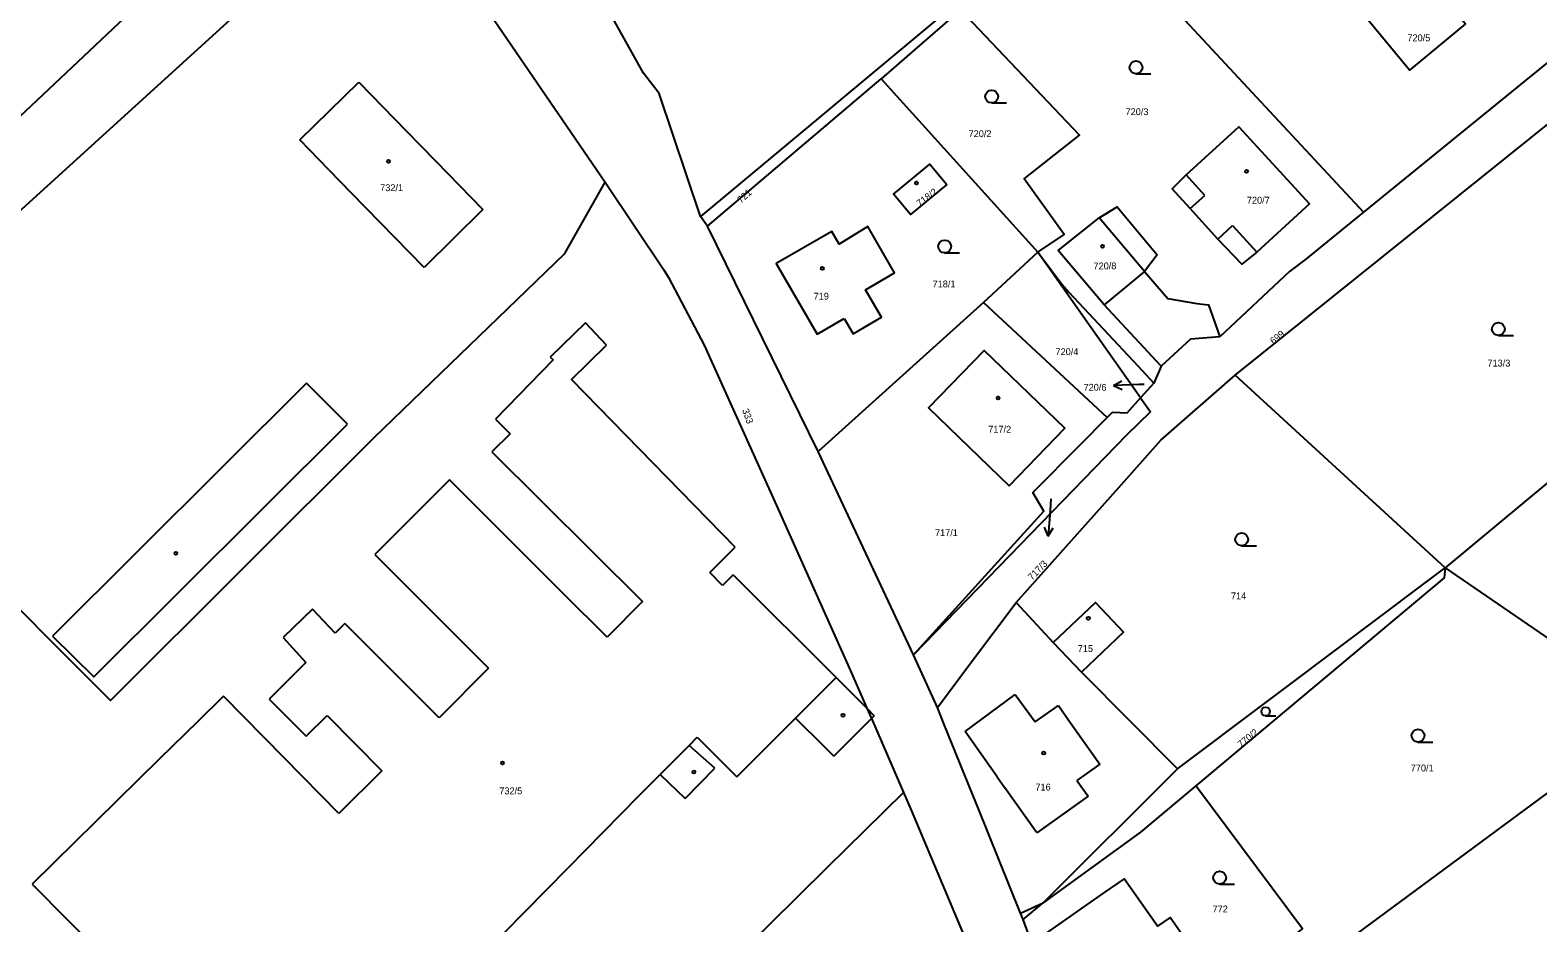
# Model space of a CAD drawing. Extents: x -719706 to -718922, y -950351 to -949651.
# Drawn here: x -719485 to -719308.7, y -949961.1 to -949856.8 of the extents above; entities that cross this region are included whole.
import ezdxf

# ---------------------------------------------------------------- set-up
doc = ezdxf.new("R2010")
doc.units = 0
doc.layers.add('Doplňující texty', color=7, linetype='Continuous')

msp = doc.modelspace()

# ---------------------------------------------------------------- linework, layer by layer
at = {"layer": 'Doplňující texty'}
for p, q in [((-719339.21, -949822.33), (-719406.63, -949878.59)), ((-719452.8, -949835.44), (-719497.78, -949877.76)), ((-719442.6, -949838.3), (-719510.6, -949900.1)), ((-719442.6, -949838.3), (-719417.75, -949874.56)), ((-719362.32, -949842.36), (-719329.12, -949878.08)), ((-719376.23, -949854.42), (-719385.52, -949862.47)), ((-719301.23, -949855.39), (-719329.12, -949878.08)), ((-719355.71, -949861.9), (-719353.96, -949861.9)), ((-719453.47, -949869.63), (-719446.57, -949862.89)), ((-719446.57, -949862.89), (-719440.99, -949868.6)), ((-719405.82, -949879.72), (-719385.52, -949862.47)), ((-719385.52, -949862.47), (-719367.2, -949882.75)), ((-719372.58, -949865.31), (-719370.83, -949865.31)), ((-719344.12, -949897.13), (-719306.59, -949867.02)), ((-719440.99, -949868.6), (-719437.57, -949872.1)), ((-719450.06, -949873.13), (-719453.47, -949869.63)), ((-719437.57, -949872.1), (-719432.08, -949877.76)), ((-719450.06, -949873.13), (-719447.46, -949875.79)), ((-719347.66, -949876.12), (-719349.85, -949873.72)), ((-719438.93, -949884.52), (-719447.46, -949875.79)), ((-719349.38, -949877.65), (-719347.66, -949876.12)), ((-719432.08, -949877.76), (-719438.93, -949884.52)), ((-719405.82, -949879.72), (-719406.63, -949878.59)), ((-719392.88, -949906.02), (-719405.82, -949879.72)), ((-719354.71, -949885), (-719360.03, -949878.73)), ((-719346.13, -949881.21), (-719344.43, -949879.64)), ((-719344.43, -949879.64), (-719341.58, -949882.74)), ((-719378.08, -949882.83), (-719376.33, -949882.83)), ((-719367.2, -949882.75), (-719373.55, -949888.61)), ((-719355.18, -949899.78), (-719367.2, -949882.75)), ((-719354.71, -949885), (-719359.44, -949888.89)), ((-719373.55, -949888.61), (-719392.88, -949906.02)), ((-719373.55, -949888.61), (-719359.07, -949902.04)), ((-719420.05, -949891.01), (-719424.19, -949895.01)), ((-719417.61, -949893.61), (-719420.05, -949891.01)), ((-719421.7, -949897.6), (-719417.61, -949893.61)), ((-719313.34, -949892.47), (-719311.59, -949892.47)), ((-719423.85, -949895.34), (-719430.59, -949902.25)), ((-719424.19, -949895.01), (-719423.85, -949895.34)), ((-719352.75, -949896.05), (-719353.61, -949898.05)), ((-719319.57, -949919.64), (-719344.12, -949897.13)), ((-719452.67, -949898.04), (-719482.37, -949927.62)), ((-719447.88, -949902.85), (-719452.67, -949898.04)), ((-719402.57, -949917.19), (-719421.7, -949897.6)), ((-719358.33, -949898.32), (-719357.35, -949897.78)), ((-719355.33, -949898.21), (-719358.33, -949898.32)), ((-719358.33, -949898.32), (-719357.31, -949898.78)), ((-719354.74, -949898.19), (-719355.33, -949898.21)), ((-719353.61, -949898.05), (-719355.18, -949899.78)), ((-719430.59, -949902.25), (-719428.89, -949903.95)), ((-719477.56, -949932.34), (-719447.88, -949902.85)), ((-719428.89, -949903.95), (-719431.02, -949906.08)), ((-719431.02, -949906.08), (-719413.39, -949923.54)), ((-719381.72, -949929.77), (-719392.88, -949906.02)), ((-719435.97, -949909.34), (-719444.69, -949918.08)), ((-719422.67, -949922.61), (-719435.97, -949909.34)), ((-719365.65, -949911.58), (-719365.75, -949912.92)), ((-719365.75, -949912.92), (-719365.96, -949915.91)), ((-719365.96, -949915.91), (-719366.39, -949914.88)), ((-719365.96, -949915.91), (-719365.39, -949914.95)), ((-719444.69, -949918.08), (-719431.39, -949931.35)), ((-719405.55, -949920.18), (-719402.57, -949917.19)), ((-719343.36, -949917.05), (-719341.61, -949917.05)), ((-719404.04, -949921.68), (-719405.55, -949920.18)), ((-719350.86, -949943.1), (-719319.57, -949919.64)), ((-719402.81, -949920.44), (-719404.04, -949921.68)), ((-719402.81, -949920.44), (-719390.78, -949932.44)), ((-719417.54, -949927.72), (-719422.67, -949922.61)), ((-719413.39, -949923.54), (-719417.54, -949927.72)), ((-719369.73, -949923.66), (-719365.41, -949928.34)), ((-719452, -949924.47), (-719455.42, -949927.78)), ((-719449.33, -949927.25), (-719452, -949924.47)), ((-719448.22, -949926.14), (-719449.33, -949927.25)), ((-719437.18, -949937.16), (-719448.22, -949926.14)), ((-719482.37, -949927.62), (-719477.56, -949932.34)), ((-719455.42, -949927.78), (-719452.75, -949930.68)), ((-719365.41, -949928.34), (-719362.09, -949931.8)), ((-719452.75, -949930.68), (-719457.04, -949934.98)), ((-719378.91, -949935.94), (-719381.72, -949929.77)), ((-719431.39, -949931.35), (-719437.18, -949937.16)), ((-719395.53, -949937.19), (-719390.78, -949932.44)), ((-719390.78, -949932.44), (-719387.18, -949936.03)), ((-719362.09, -949931.8), (-719350.86, -949943.1)), ((-719375.69, -949938.74), (-719369.82, -949934.44)), ((-719369.82, -949934.44), (-719367.48, -949937.63)), ((-719462.38, -949934.6), (-719465.36, -949937.52)), ((-719455.28, -949941.83), (-719462.38, -949934.6)), ((-719457.04, -949934.98), (-719452.72, -949939.31)), ((-719387.18, -949936.03), (-719386.31, -949936.9)), ((-719367.48, -949937.63), (-719364.77, -949935.72)), ((-719364.77, -949935.72), (-719363.55, -949937.45)), ((-719465.36, -949937.52), (-719469.87, -949941.95)), ((-719452.72, -949939.31), (-719450.25, -949936.88)), ((-719450.25, -949936.88), (-719443.88, -949943.36)), ((-719402.36, -949944.04), (-719395.53, -949937.19)), ((-719395.53, -949937.19), (-719392.13, -949940.55)), ((-719391.04, -949941.63), (-719386.65, -949937.24)), ((-719386.31, -949936.9), (-719386.65, -949937.24)), ((-719363.55, -949937.45), (-719362.69, -949938.66)), ((-719340.55, -949936.91), (-719339.37, -949936.91)), ((-719407.96, -949940.37), (-719407, -949939.41)), ((-719407, -949939.41), (-719402.36, -949944.04)), ((-719371.95, -949944.03), (-719375.69, -949938.74)), ((-719362.69, -949938.66), (-719359.93, -949942.56)), ((-719407.96, -949940.37), (-719411.35, -949943.77)), ((-719404.96, -949943.04), (-719407.96, -949940.37)), ((-719391.04, -949941.63), (-719392.13, -949940.55)), ((-719322.75, -949939.98), (-719321, -949939.98)), ((-719469.87, -949941.95), (-719484.76, -949956.58)), ((-719448.91, -949948.31), (-719455.28, -949941.83)), ((-719408.42, -949946.56), (-719404.96, -949943.04)), ((-719366.57, -949958.76), (-719350.86, -949943.1)), ((-719359.93, -949942.56), (-719362.62, -949944.46)), ((-719443.88, -949943.36), (-719448.91, -949948.31)), ((-719413.86, -949946.31), (-719411.35, -949943.77)), ((-719411.35, -949943.77), (-719408.42, -949946.56)), ((-719371.95, -949944.03), (-719371.04, -949945.32)), ((-719362.62, -949944.46), (-719361.31, -949946.31)), ((-719413.86, -949946.31), (-719422.15, -949954.73)), ((-719367.32, -949950.57), (-719371.04, -949945.32)), ((-719361.31, -949946.31), (-719367.32, -949950.57)), ((-719432.15, -949964.86), (-719422.15, -949954.73)), ((-719484.76, -949956.58), (-719458.38, -949983.18)), ((-719345.93, -949956.58), (-719344.18, -949956.58)), ((-719369.21, -949959.98), (-719366.57, -949958.76)), ((-719368.91, -949960.71), (-719366.57, -949958.76)), ((-719367.88, -949963.49), (-719368.91, -949960.71))]:
    msp.add_line(p, q, dxfattribs=at)
for points in [[(-719317.18, -949856.06), (-719323.74, -949861.48), (-719330.42, -949853.38), (-719323.87, -949847.96), (-719317.18, -949856.06)], [(-719406.63, -949878.59), (-719411.45, -949864.22), (-719413.3, -949861.83), (-719419.49, -949850.7)], [(-719367.2, -949882.75), (-719364.09, -949880.68), (-719368.8, -949874.17), (-719362.32, -949869.09), (-719376.23, -949854.42)], [(-719335.42, -949877.08), (-719341.58, -949882.74), (-719343.34, -949884.16), (-719346.13, -949881.21), (-719349.38, -949877.65), (-719351.47, -949875.33), (-719349.85, -949873.72), (-719343.67, -949868.08), (-719335.42, -949877.08)], [(-719377.84, -949874.82), (-719382.06, -949878.35), (-719384.05, -949875.97), (-719379.82, -949872.44), (-719377.84, -949874.82)], [(-719510.6, -949900.1), (-719475.6, -949935.11), (-719444.77, -949904.38), (-719422.48, -949882.88), (-719417.75, -949874.56)], [(-719417.75, -949874.56), (-719410.92, -949884.79), (-719410.37, -949885.69), (-719406.19, -949893.61), (-719397.74, -949912.35), (-719389.24, -949931.32), (-719387.18, -949936.03), (-719386.65, -949937.24), (-719382.88, -949945.88)], [(-719263.73, -949873.25), (-719265.07, -949874.36), (-719319.57, -949919.64)], [(-719352.75, -949896.05), (-719359.44, -949888.89), (-719364.81, -949882.53), (-719360.03, -949878.73), (-719357.9, -949877.43), (-719353.23, -949883.05), (-719354.71, -949885), (-719351.97, -949888.16), (-719348.59, -949888.72), (-719347.25, -949888.9), (-719345.91, -949892.65)], [(-719329.12, -949878.08), (-719335.84, -949883.55), (-719337.78, -949884.99), (-719345.91, -949892.65)], [(-719389.81, -949890.5), (-719388.79, -949892.27), (-719385.47, -949890.35), (-719387.33, -949887.13), (-719383.94, -949885.17), (-719387.06, -949879.76), (-719390.42, -949881.8), (-719391.27, -949880.32), (-719397.76, -949884.06), (-719392.98, -949892.33), (-719389.81, -949890.5)], [(-719367.2, -949882.75), (-719366.35, -949883.84), (-719364.33, -949886.53), (-719363.57, -949887.42), (-719355.51, -949896.02), (-719353.61, -949898.05)], [(-719345.91, -949892.65), (-719349.32, -949892.89), (-719352.75, -949896.05)], [(-719370.55, -949910.04), (-719364.03, -949903.31), (-719373.45, -949894.22), (-719379.95, -949900.94), (-719370.55, -949910.04)], [(-719369.73, -949923.66), (-719357.4, -949909.9), (-719352.8, -949904.71), (-719344.12, -949897.13)], [(-719355.18, -949899.78), (-719354.03, -949901.41), (-719356.81, -949904.14), (-719381.72, -949929.77)], [(-719359.07, -949902.04), (-719358.47, -949901.42), (-719356.75, -949901.53), (-719355.18, -949899.78)], [(-719381.72, -949929.77), (-719366.5, -949913), (-719367.78, -949910.82), (-719362.18, -949905.22), (-719359.07, -949902.04)], [(-719319.57, -949919.64), (-719319.69, -949920.8), (-719348.71, -949945.09)], [(-719319.57, -949919.64), (-719298.98, -949933.71), (-719295.41, -949935.76)], [(-719378.91, -949935.94), (-719375.05, -949930.77), (-719369.73, -949923.66)], [(-719365.41, -949928.34), (-719360.46, -949923.66), (-719357.17, -949927.15), (-719362.09, -949931.8)], [(-719368.91, -949960.71), (-719369.21, -949959.98), (-719374.21, -949947.57), (-719374.83, -949946.07), (-719378.12, -949937.91), (-719378.91, -949935.94)], [(-719295.41, -949935.76), (-719294.77, -949936.44), (-719329.97, -949962.44), (-719347.58, -949977.67)], [(-719348.71, -949945.09), (-719349.41, -949945.69), (-719355.17, -949950.5), (-719366.57, -949958.76)], [(-719357.52, -949978.4), (-719349.26, -949972.09), (-719336.24, -949961.8), (-719348.71, -949945.09)], [(-719382.88, -949945.88), (-719391.85, -949954.68), (-719455.66, -950017.69), (-719499.55, -950048.33)], [(-719382.88, -949945.88), (-719382, -949947.95), (-719373.91, -949967.08)], [(-719357.52, -949978.4), (-719358.46, -949977.05), (-719350.01, -949971.03), (-719352.89, -949966.91), (-719350.56, -949965.27), (-719349.09, -949964.23), (-719351.72, -949960.46), (-719353.2, -949961.49), (-719357.11, -949955.95), (-719359.43, -949957.57), (-719367.88, -949963.49)]]:
    msp.add_lwpolyline(points, dxfattribs=at)
for centre, radius in [((-719355.71, -949861.15), 0.75), ((-719372.58, -949864.56), 0.75), ((-719443.1, -949872.14), 0.175), ((-719381.36, -949874.67), 0.175), ((-719342.79, -949873.3), 0.175), ((-719378.08, -949882.08), 0.75), ((-719359.63, -949882.05), 0.175), ((-719392.38, -949884.64), 0.175), ((-719313.34, -949891.72), 0.75), ((-719371.82, -949899.79), 0.175), ((-719343.36, -949916.3), 0.75), ((-719467.97, -949917.91), 0.175), ((-719361.28, -949925.52), 0.175), ((-719340.55, -949936.41), 0.502), ((-719389.96, -949936.85), 0.175), ((-719322.75, -949939.23), 0.75), ((-719366.5, -949941.26), 0.175), ((-719429.77, -949942.41), 0.175), ((-719407.4, -949943.48), 0.175), ((-719345.93, -949955.83), 0.75)]:
    msp.add_circle(centre, radius, dxfattribs=at)

# ---------------------------------------------------------------- texts
for s, p in [('720/5', (-719323.98, -949858.1)), ('720/3', (-719356.93, -949866.73)), ('720/2', (-719375.28, -949869.3)), ('732/1', (-719444.07, -949875.61)), ('720/7', (-719342.75, -949877.07)), ('720/8', (-719360.68, -949884.75)), ('718/1', (-719379.49, -949886.86)), ('719', (-719393.4, -949888.29)), ('720/4', (-719365.12, -949894.77)), ('713/3', (-719314.62, -949896.1)), ('720/6', (-719361.84, -949898.93)), ('717/2', (-719372.98, -949903.83)), ('717/1', (-719379.21, -949915.92)), ('714', (-719344.61, -949923.3)), ('715', (-719362.52, -949929.45)), ('770/1', (-719323.59, -949943.41)), ('716', (-719367.47, -949945.64)), ('732/5', (-719430.14, -949946.08)), ('772', (-719346.76, -949959.88))]:
    msp.add_text(s, height=0.8, dxfattribs=at).set_placement(p)
for s, rotation, p in [('721', 42, (-719401.89, -949877.08)), ('718/2', 37, (-719380.99, -949877.46)), ('699', 39, (-719339.64, -949893.56)), ('333', 290, (-719401.77, -949901.19)), ('717/3', 46, (-719367.85, -949921.14)), ('770/2', 39, (-719343.43, -949940.66))]:
    msp.add_text(s, height=0.8, rotation=rotation, dxfattribs=at).set_placement(p)

doc.saveas('drawing.dxf')
